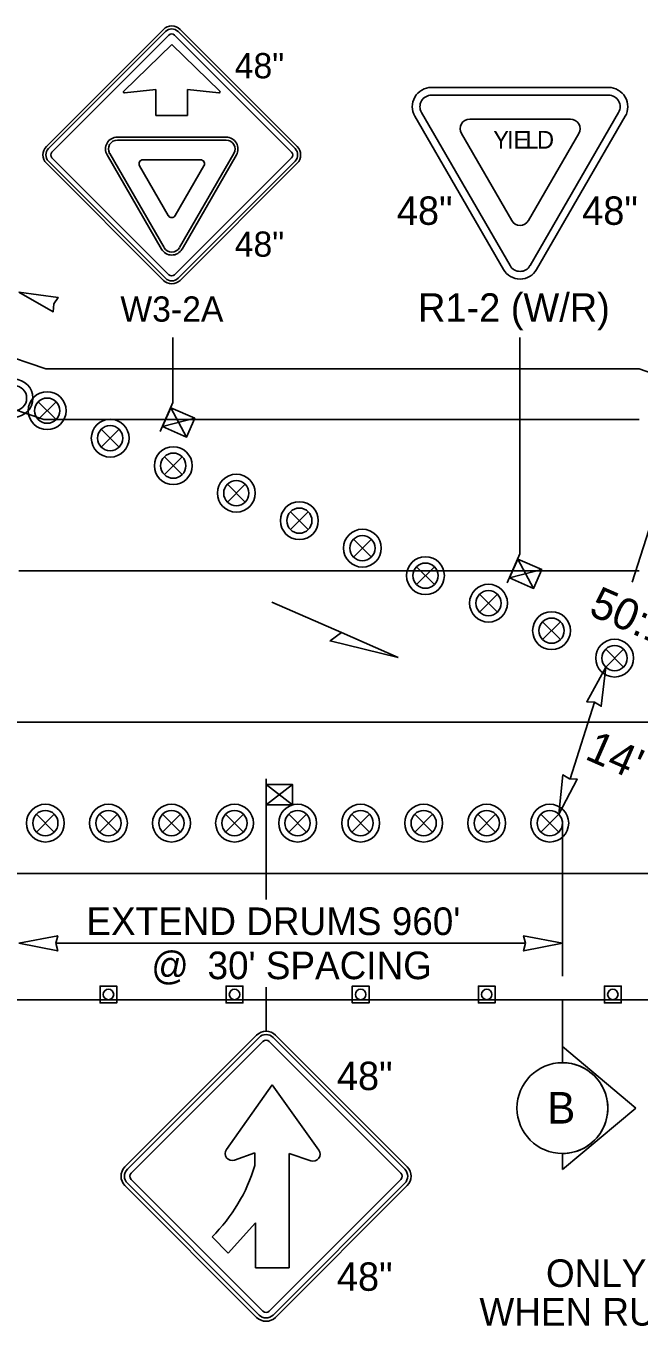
# Model space of a CAD drawing. Extents: x 99999 to 100116, y 99995 to 100013.
# Drawn here: x 100090.62 to 100092.176, y 100005.732 to 100009.03 of the extents above; entities that cross this region are included whole.
import ezdxf

# ---------------------------------------------------------------- set-up
doc = ezdxf.new("R2010")
doc.units = 0
for name, color, linetype in [('Default', 7, 'Continuous'), ('RD_MK_LineEdgeYellow', 7, 'Continuous'), ('RD_MK_LineLane', 7, 'Continuous'), ('SH_GI_SectionCut', 7, 'Continuous'), ('TR_SN_ConstructionSigns', 7, 'Continuous'), ('TR_WZ_PortableSignMount5ftMinBlk-Org', 7, 'Continuous'), ('TR_WZ_PortableSignMount5ftMinRed-Wht', 7, 'Continuous'), ('TR_WZ_TrafficCone', 7, 'Continuous'), ('TR_WZ_TrafficSafetyDrum', 7, 'Continuous'), ('TR_WZ_WorkZoneDetails', 7, 'Continuous'), ('TR_WZ_WorkZoneTextCurrent', 7, 'Continuous')]:
    doc.layers.add(name, color=color, linetype=linetype)

msp = doc.modelspace()

# ---------------------------------------------------------------- linework, layer by layer
at = {"layer": 'Default'}
for p, q in [((100090.9689, 100009.0212), (100090.6719, 100008.7242)), ((100091.3083, 100008.7242), (100091.0113, 100009.0212)), ((100090.6719, 100008.6818), (100090.9689, 100008.3848)), ((100091.0113, 100008.3848), (100091.3083, 100008.6818)), ((100091.2055, 100006.4701), (100090.8714, 100006.136)), ((100091.5873, 100006.136), (100091.2532, 100006.4701)), ((100090.8714, 100006.0883), (100091.2055, 100005.7542)), ((100091.2532, 100005.7542), (100091.5873, 100006.0883))]:
    msp.add_line(p, q, dxfattribs=at)
for centre, radius, start, end in [((100090.9901, 100009), 0.03, 45, 135), ((100090.6931, 100008.703), 0.03, 135, 225), ((100091.2871, 100008.703), 0.03, 315, 45), ((100090.9901, 100008.406), 0.03, 225, 315), ((100091.2294, 100006.4463), 0.0338, 45, 135), ((100090.8953, 100006.1122), 0.0338, 135, 225), ((100091.5635, 100006.1122), 0.0338, 315, 45), ((100091.2294, 100005.7781), 0.0338, 225, 315)]:
    msp.add_arc(centre, radius, start, end, dxfattribs=at)
at = {"layer": 'RD_MK_LineEdgeYellow'}
for p, q in [((100088.195, 100008.8663), (100090.6655, 100008.032)), ((100090.6655, 100008.032), (100092.1758, 100008.032)), ((100088.195, 100006.88), (100095.43, 100006.88))]:
    msp.add_line(p, q, dxfattribs=at)
at = {"layer": 'RD_MK_LineLane'}
for points in [[(100092.1758, 100007.648), (100090.6024, 100007.648)], [(100095.43, 100007.264), (100088.195, 100007.264)]]:
    msp.add_lwpolyline(points, dxfattribs=at)
at = {"layer": 'SH_GI_SectionCut'}
for p, q in [((100092.1583, 100007.619), (100092.3791, 100008.3098)), ((100091.9814, 100006.441), (100091.9814, 100006.56)), ((100091.9814, 100006.441), (100091.9814, 100006.4003)), ((100092.1675, 100006.2851), (100091.9814, 100006.441)), ((100091.9814, 100006.1292), (100092.1675, 100006.2851)), ((100091.9814, 100006.1699), (100091.9814, 100006.1292))]:
    msp.add_line(p, q, dxfattribs=at)
msp.add_circle((100091.9814, 100006.2851), 0.1152, dxfattribs=at)
msp.add_circle((100091.9814, 100006.2851), 0.1152, dxfattribs=at)
for start, end in [(90.0028, 269.9984), (269.9984, 90.0028), (269.9984, 90.0028)]:
    msp.add_arc((100091.9814, 100006.2851), 0.1152, start, end, dxfattribs=at)
at = {"layer": 'TR_SN_ConstructionSigns'}
for p, q in [((100090.6719, 100008.7242), (100090.9689, 100009.0212)), ((100090.9742, 100009.0159), (100090.6772, 100008.7189)), ((100091.303, 100008.7189), (100091.006, 100009.0159)), ((100091.0113, 100009.0212), (100091.3083, 100008.7242)), ((100090.686, 100008.7101), (100090.983, 100009.0071)), ((100090.9901, 100008.983), (100090.8683, 100008.8648)), ((100091.1118, 100008.8648), (100090.9901, 100008.983)), ((100090.9971, 100009.0071), (100091.2941, 100008.7101)), ((100090.8703, 100008.8605), (100090.9501, 100008.8688)), ((100090.9501, 100008.8688), (100090.9501, 100008.803)), ((100091.0301, 100008.803), (100091.0301, 100008.8688)), ((100091.0301, 100008.8688), (100091.1098, 100008.8605)), ((100092.0987, 100008.874), (100091.6491, 100008.874)), ((100091.6491, 100008.8545), (100091.6491, 100008.8547)), ((100091.6491, 100008.8547), (100091.8739, 100008.8547)), ((100091.8739, 100008.8547), (100091.6491, 100008.8547)), ((100091.6491, 100008.8547), (100091.6491, 100008.8545)), ((100090.9501, 100008.803), (100091.0301, 100008.803)), ((100091.8317, 100008.4123), (100091.6069, 100008.8009)), ((100091.6069, 100008.8009), (100091.8317, 100008.4123)), ((100091.8486, 100008.4221), (100091.6238, 100008.8107)), ((100091.6238, 100008.8107), (100091.8486, 100008.4221)), ((100091.8739, 100008.7938), (100091.7461, 100008.7938)), ((100091.7461, 100008.7938), (100091.8739, 100008.7938)), ((100092.0017, 100008.7938), (100091.8739, 100008.7938)), ((100091.8739, 100008.7938), (100092.0017, 100008.7938)), ((100092.124, 100008.8107), (100091.8992, 100008.4221)), ((100091.8992, 100008.4221), (100092.124, 100008.8107)), ((100092.1408, 100008.8009), (100091.916, 100008.4123)), ((100091.916, 100008.4123), (100092.1408, 100008.8009)), ((100091.725, 100008.7573), (100091.8528, 100008.5364)), ((100091.8528, 100008.5364), (100091.725, 100008.7573)), ((100091.895, 100008.5364), (100092.0228, 100008.7573)), ((100092.0228, 100008.7573), (100091.895, 100008.5364)), ((100091.1281, 100008.748), (100090.852, 100008.748)), ((100090.852, 100008.7405), (100091.1281, 100008.7405)), ((100091.1281, 100008.7405), (100090.852, 100008.7405)), ((100090.6772, 100008.6871), (100090.9742, 100008.3901)), ((100090.983, 100008.399), (100090.686, 100008.6959)), ((100090.8261, 100008.703), (100090.9641, 100008.4639)), ((100090.9706, 100008.4677), (100090.8326, 100008.7068)), ((100090.8326, 100008.7068), (100090.9706, 100008.4677)), ((100091.0632, 100008.6905), (100090.917, 100008.6905)), ((100090.917, 100008.6905), (100091.0632, 100008.6905)), ((100091.2941, 100008.6959), (100090.9971, 100008.399)), ((100091.006, 100008.3901), (100091.303, 100008.6871)), ((100091.1476, 100008.7068), (100091.0096, 100008.4677)), ((100091.0096, 100008.4677), (100091.1476, 100008.7068)), ((100091.0161, 100008.4639), (100091.1541, 100008.703)), ((100090.9689, 100008.3848), (100090.6719, 100008.6818)), ((100090.9083, 100008.6755), (100090.9814, 100008.5489)), ((100090.9814, 100008.5489), (100090.9083, 100008.6755)), ((100090.9987, 100008.5489), (100091.0718, 100008.6755)), ((100091.0718, 100008.6755), (100090.9987, 100008.5489)), ((100091.3083, 100008.6818), (100091.0113, 100008.3848)), ((100090.8714, 100006.136), (100091.2055, 100006.4701)), ((100091.2115, 100006.4642), (100090.8774, 100006.1301)), ((100090.8873, 100006.1201), (100091.2214, 100006.4542)), ((100091.2373, 100006.4542), (100091.5714, 100006.1201)), ((100091.5814, 100006.1301), (100091.2473, 100006.4642)), ((100091.2532, 100006.4701), (100091.5873, 100006.136)), ((100091.2453, 100006.3441), (100091.1288, 100006.1802)), ((100091.3632, 100006.1784), (100091.2453, 100006.3441)), ((100091.1493, 100006.1532), (100091.2012, 100006.1718)), ((100091.2012, 100006.1718), (100091.2012, 100006.1394)), ((100091.288, 100005.8802), (100091.288, 100006.1703)), ((100091.288, 100006.1703), (100091.3429, 100006.1513)), ((100091.2055, 100005.7542), (100090.8714, 100006.0883)), ((100090.8774, 100006.0943), (100091.2115, 100005.7602)), ((100091.2214, 100005.7701), (100090.8873, 100006.1042)), ((100091.5714, 100006.1042), (100091.2373, 100005.7701)), ((100091.2473, 100005.7602), (100091.5814, 100006.0943)), ((100091.5873, 100006.0883), (100091.2532, 100005.7542)), ((100091.1335, 100005.9171), (100091.2027, 100005.9936)), ((100091.2027, 100005.9936), (100091.2027, 100005.8802)), ((100091.0923, 100005.9583), (100091.1335, 100005.9171)), ((100091.2027, 100005.8802), (100091.288, 100005.8802))]:
    msp.add_line(p, q, dxfattribs=at)
for points in [[(100091.6491, 100008.874), (100092.0987, 100008.874)], [(100091.8739, 100008.8547), (100092.0987, 100008.8547), (100092.0987, 100008.8545)], [(100092.0987, 100008.8545), (100092.0987, 100008.8547), (100091.8739, 100008.8547)]]:
    msp.add_lwpolyline(points, dxfattribs=at)
for centre, radius, start, end in [((100090.9901, 100009), 0.03, 45, 135), ((100090.9901, 100009), 0.0225, 45, 135), ((100090.9901, 100009), 0.01, 45, 135), ((100090.8701, 100008.863), 0.0025, 134.1559, 275.9533), ((100091.1101, 100008.863), 0.0025, 264.0467, 45.8441), ((100091.6491, 100008.8253), 0.0487, 90, 210.0517), ((100091.6491, 100008.8253), 0.0487, 90, 210.0517), ((100091.6491, 100008.8253), 0.0292, 90, 210.0517), ((100091.6491, 100008.8253), 0.0292, 90, 210.0517), ((100092.0987, 100008.8253), 0.0487, 329.9522, 90), ((100092.0987, 100008.8253), 0.0487, 329.9522, 90), ((100092.0987, 100008.8253), 0.0292, 329.9522, 90), ((100092.0987, 100008.8253), 0.0292, 329.9522, 90), ((100091.7461, 100008.7695), 0.0244, 90, 210.0513), ((100091.7461, 100008.7695), 0.0244, 90, 210.0513), ((100092.0017, 100008.7695), 0.0244, 329.9514, 90), ((100092.0017, 100008.7695), 0.0244, 329.9514, 90), ((100090.6931, 100008.703), 0.03, 135, 225), ((100090.6931, 100008.703), 0.0225, 135, 225), ((100090.852, 100008.718), 0.03, 90, 210), ((100090.852, 100008.718), 0.0225, 90, 210), ((100090.852, 100008.718), 0.0225, 90, 210), ((100091.1281, 100008.718), 0.03, 330, 90), ((100091.1281, 100008.718), 0.0225, 330, 90), ((100091.1281, 100008.718), 0.0225, 330, 90), ((100091.2871, 100008.703), 0.0225, 315, 45), ((100091.2871, 100008.703), 0.03, 315, 45), ((100090.6931, 100008.703), 0.01, 135, 225), ((100090.917, 100008.6805), 0.01, 90, 210), ((100090.917, 100008.6805), 0.01, 90, 210), ((100091.0632, 100008.6805), 0.01, 330, 90), ((100091.0632, 100008.6805), 0.01, 330, 90), ((100091.2871, 100008.703), 0.01, 315, 45), ((100090.9901, 100008.5539), 0.01, 210, 330), ((100090.9901, 100008.5539), 0.01, 210, 330), ((100091.8739, 100008.5486), 0.0244, 210.0519, 329.9525), ((100091.8739, 100008.5486), 0.0244, 210.0519, 329.9525), ((100090.9901, 100008.4789), 0.03, 210, 330), ((100090.9901, 100008.4789), 0.0225, 210, 330), ((100090.9901, 100008.4789), 0.0225, 210, 330), ((100091.8739, 100008.4367), 0.0292, 210.0518, 329.9516), ((100091.8739, 100008.4367), 0.0292, 210.0518, 329.9516), ((100090.9901, 100008.406), 0.0225, 225, 315), ((100090.9901, 100008.406), 0.01, 225, 315), ((100091.8739, 100008.4367), 0.0487, 210.0518, 329.9516), ((100091.8739, 100008.4367), 0.0487, 210.0518, 329.9516), ((100090.9901, 100008.406), 0.03, 225, 315), ((100091.2294, 100006.4463), 0.0338, 45, 135), ((100091.2294, 100006.4463), 0.0253, 45, 135), ((100091.2294, 100006.4463), 0.0113, 45, 135), ((100091.1433, 100006.17), 0.0177, 144.5862, 289.6669), ((100091.3487, 100006.1681), 0.0177, 250.8938, 35.4138), ((100090.8953, 100006.1122), 0.0338, 135, 225), ((100090.8953, 100006.1122), 0.0253, 135, 225), ((100090.8953, 100006.1122), 0.0113, 135, 225), ((100090.7881, 100006.2645), 0.4316, 314.815, 343.157), ((100091.5635, 100006.1122), 0.0113, 315, 45), ((100091.5635, 100006.1122), 0.0253, 315, 45), ((100091.5635, 100006.1122), 0.0338, 315, 45), ((100091.2294, 100005.7781), 0.0338, 225, 315), ((100091.2294, 100005.7781), 0.0253, 225, 315), ((100091.2294, 100005.7781), 0.0113, 225, 315)]:
    msp.add_arc(centre, radius, start, end, dxfattribs=at)
at = {"layer": 'TR_WZ_PortableSignMount5ftMinBlk-Org'}
for p, q in [((100090.9931, 100008.0746), (100090.9611, 100008.0012)), ((100091.0279, 100007.9874), (100090.9875, 100008.0617)), ((100091.0486, 100008.0351), (100090.9667, 100008.0141)), ((100091.0077, 100008.0246), (100091.0077, 100008.0246)), ((100091.0078, 100008.0245), (100091.0078, 100008.0245)), ((100091.2294, 100007.12), (100091.2294, 100007.04)), ((100091.2961, 100007.054), (100091.2294, 100007.106)), ((100091.2961, 100007.106), (100091.2294, 100007.054)), ((100091.2627, 100007.08), (100091.2627, 100007.08)), ((100091.2628, 100007.08), (100091.2628, 100007.08))]:
    msp.add_line(p, q, dxfattribs=at)
for points in [[(100091.0279, 100007.9874), (100091.0486, 100008.0351), (100090.9875, 100008.0617), (100090.9667, 100008.0141)], [(100090.9875, 100008.0617), (100091.0486, 100008.0351), (100091.0279, 100007.9874), (100090.9667, 100008.0141)], [(100091.2961, 100007.054), (100091.2961, 100007.106), (100091.2294, 100007.106), (100091.2294, 100007.054)], [(100091.2294, 100007.106), (100091.2961, 100007.106), (100091.2961, 100007.054), (100091.2294, 100007.054)]]:
    msp.add_lwpolyline(points, close=True, dxfattribs=at)
at = {"layer": 'TR_WZ_PortableSignMount5ftMinRed-Wht'}
for p, q in [((100091.8736, 100007.6907), (100091.8416, 100007.6174)), ((100091.9083, 100007.6035), (100091.868, 100007.6778)), ((100091.9291, 100007.6511), (100091.8472, 100007.6302)), ((100091.8881, 100007.6407), (100091.8881, 100007.6407)), ((100091.8882, 100007.6406), (100091.8882, 100007.6406))]:
    msp.add_line(p, q, dxfattribs=at)
for points in [[(100091.9083, 100007.6035), (100091.9291, 100007.6511), (100091.868, 100007.6778), (100091.8472, 100007.6302)], [(100091.868, 100007.6778), (100091.9291, 100007.6511), (100091.9083, 100007.6035), (100091.8472, 100007.6302)]]:
    msp.add_lwpolyline(points, close=True, dxfattribs=at)
at = {"layer": 'TR_WZ_TrafficCone'}
for points in [[(100090.8081, 100006.552), (100090.8507, 100006.552), (100090.8507, 100006.5947), (100090.8081, 100006.5947), (100090.8081, 100006.552)], [(100090.8081, 100006.5947), (100090.8507, 100006.5947), (100090.8507, 100006.552), (100090.8081, 100006.552), (100090.8081, 100006.5947)], [(100091.1281, 100006.552), (100091.1707, 100006.552), (100091.1707, 100006.5947), (100091.1281, 100006.5947), (100091.1281, 100006.552)], [(100091.1281, 100006.5947), (100091.1707, 100006.5947), (100091.1707, 100006.552), (100091.1281, 100006.552), (100091.1281, 100006.5947)], [(100091.4481, 100006.552), (100091.4907, 100006.552), (100091.4907, 100006.5947), (100091.4481, 100006.5947), (100091.4481, 100006.552)], [(100091.4481, 100006.5947), (100091.4907, 100006.5947), (100091.4907, 100006.552), (100091.4481, 100006.552), (100091.4481, 100006.5947)], [(100091.7681, 100006.552), (100091.8107, 100006.552), (100091.8107, 100006.5947), (100091.7681, 100006.5947), (100091.7681, 100006.552)], [(100091.7681, 100006.5947), (100091.8107, 100006.5947), (100091.8107, 100006.552), (100091.7681, 100006.552), (100091.7681, 100006.5947)], [(100092.0881, 100006.552), (100092.1307, 100006.552), (100092.1307, 100006.5947), (100092.0881, 100006.5947), (100092.0881, 100006.552)], [(100092.0881, 100006.5947), (100092.1307, 100006.5947), (100092.1307, 100006.552), (100092.0881, 100006.552), (100092.0881, 100006.5947)]]:
    msp.add_lwpolyline(points, dxfattribs=at)
for centre in [(100090.8294, 100006.5734), (100091.1494, 100006.5734), (100091.4694, 100006.5734), (100091.7894, 100006.5734), (100092.1094, 100006.5734)]:
    msp.add_circle(centre, 0.0133, dxfattribs=at)
at = {"layer": 'TR_WZ_TrafficSafetyDrum'}
for p, q in [((100090.6513, 100008.0316), (100090.6966, 100008.0768)), ((100090.6966, 100008.0316), (100090.6513, 100008.0768)), ((100090.8113, 100007.9618), (100090.8566, 100008.0071)), ((100090.8566, 100007.9618), (100090.8113, 100008.0071)), ((100090.9713, 100007.8921), (100091.0166, 100007.9373)), ((100091.0166, 100007.8921), (100090.9713, 100007.9373)), ((100091.1313, 100007.8223), (100091.1766, 100007.8676)), ((100091.1766, 100007.8223), (100091.1313, 100007.8676)), ((100091.2913, 100007.7526), (100091.3366, 100007.7978)), ((100091.3366, 100007.7526), (100091.2913, 100007.7978)), ((100091.4513, 100007.6828), (100091.4966, 100007.7281)), ((100091.4966, 100007.6828), (100091.4513, 100007.7281)), ((100091.6113, 100007.6131), (100091.6566, 100007.6584)), ((100091.6566, 100007.6131), (100091.6113, 100007.6584)), ((100091.7713, 100007.5434), (100091.8166, 100007.5886)), ((100091.8166, 100007.5434), (100091.7713, 100007.5886)), ((100091.9313, 100007.4736), (100091.9766, 100007.5189)), ((100091.9766, 100007.4736), (100091.9313, 100007.5189)), ((100092.0913, 100007.4039), (100092.1366, 100007.4491)), ((100092.1366, 100007.4039), (100092.0913, 100007.4491)), ((100090.6468, 100006.9854), (100090.692, 100007.0306)), ((100090.692, 100006.9854), (100090.6468, 100007.0306)), ((100090.8068, 100006.9854), (100090.852, 100007.0306)), ((100090.852, 100006.9854), (100090.8068, 100007.0306)), ((100090.9668, 100006.9854), (100091.012, 100007.0306)), ((100091.012, 100006.9854), (100090.9668, 100007.0306)), ((100091.1268, 100006.9854), (100091.172, 100007.0306)), ((100091.172, 100006.9854), (100091.1268, 100007.0306)), ((100091.2868, 100006.9854), (100091.332, 100007.0306)), ((100091.332, 100006.9854), (100091.2868, 100007.0306)), ((100091.4468, 100006.9854), (100091.492, 100007.0306)), ((100091.492, 100006.9854), (100091.4468, 100007.0306)), ((100091.6068, 100006.9854), (100091.652, 100007.0306)), ((100091.652, 100006.9854), (100091.6068, 100007.0306)), ((100091.7668, 100006.9854), (100091.812, 100007.0306)), ((100091.812, 100006.9854), (100091.7668, 100007.0306)), ((100091.9268, 100006.9854), (100091.972, 100007.0306)), ((100091.972, 100006.9854), (100091.9268, 100007.0306))]:
    msp.add_line(p, q, dxfattribs=at)
for centre, radius in [((100090.5899, 100008.086), 0.048), ((100090.5899, 100008.086), 0.048), ((100090.5899, 100008.086), 0.032), ((100090.6739, 100008.0542), 0.048), ((100090.6739, 100008.0542), 0.048), ((100090.6739, 100008.0542), 0.032), ((100090.8339, 100007.9845), 0.048), ((100090.8339, 100007.9845), 0.048), ((100090.8339, 100007.9845), 0.032), ((100090.9939, 100007.9147), 0.048), ((100090.9939, 100007.9147), 0.048), ((100090.9939, 100007.9147), 0.032), ((100091.1539, 100007.845), 0.048), ((100091.1539, 100007.845), 0.048), ((100091.1539, 100007.845), 0.032), ((100091.3139, 100007.7752), 0.048), ((100091.3139, 100007.7752), 0.048), ((100091.3139, 100007.7752), 0.032), ((100091.4739, 100007.7055), 0.048), ((100091.4739, 100007.7055), 0.048), ((100091.4739, 100007.7055), 0.032), ((100091.6339, 100007.6357), 0.048), ((100091.6339, 100007.6357), 0.048), ((100091.6339, 100007.6357), 0.032), ((100091.7939, 100007.566), 0.048), ((100091.7939, 100007.566), 0.048), ((100091.7939, 100007.566), 0.032), ((100091.9539, 100007.4962), 0.048), ((100091.9539, 100007.4962), 0.048), ((100091.9539, 100007.4962), 0.032), ((100092.1139, 100007.4265), 0.048), ((100092.1139, 100007.4265), 0.048), ((100092.1139, 100007.4265), 0.032), ((100090.6694, 100007.008), 0.048), ((100090.6694, 100007.008), 0.048), ((100090.6694, 100007.008), 0.032), ((100090.8294, 100007.008), 0.048), ((100090.8294, 100007.008), 0.048), ((100090.8294, 100007.008), 0.032), ((100090.9894, 100007.008), 0.048), ((100090.9894, 100007.008), 0.048), ((100090.9894, 100007.008), 0.032), ((100091.1494, 100007.008), 0.048), ((100091.1494, 100007.008), 0.048), ((100091.1494, 100007.008), 0.032), ((100091.3094, 100007.008), 0.048), ((100091.3094, 100007.008), 0.048), ((100091.3094, 100007.008), 0.032), ((100091.4694, 100007.008), 0.048), ((100091.4694, 100007.008), 0.048), ((100091.4694, 100007.008), 0.032), ((100091.6294, 100007.008), 0.048), ((100091.6294, 100007.008), 0.048), ((100091.6294, 100007.008), 0.032), ((100091.7894, 100007.008), 0.048), ((100091.7894, 100007.008), 0.048), ((100091.7894, 100007.008), 0.032), ((100091.9494, 100007.008), 0.048), ((100091.9494, 100007.008), 0.048), ((100091.9494, 100007.008), 0.032)]:
    msp.add_circle(centre, radius, dxfattribs=at)
at = {"layer": 'TR_WZ_WorkZoneDetails'}
for p, q in [((100088.195, 100009.0015), (100090.6703, 100008.16)), ((100090.9931, 100008.0746), (100090.9931, 100008.24)), ((100091.8736, 100007.6907), (100091.8738, 100008.24)), ((100090.6703, 100008.16), (100092.1758, 100008.16)), ((100092.1758, 100008.16), (100092.7368, 100007.968)), ((100091.4207, 100007.4911), (100091.2441, 100007.5687)), ((100092.0007, 100007.1203), (100092.0628, 100007.3146)), ((100091.2294, 100007.04), (100091.2294, 100006.8141)), ((100091.9814, 100006.6197), (100091.9814, 100007.0134)), ((100091.8876, 100006.7031), (100090.6962, 100006.7031)), ((100091.2294, 100006.5921), (100091.2294, 100006.48)), ((100088.195, 100006.56), (100095.43, 100006.56))]:
    msp.add_line(p, q, dxfattribs=at)
for points in [[(100090.6024, 100008.355), (100090.6893, 100008.3051), (100090.6912, 100008.3249), (100090.7017, 100008.3416)], [(100091.5646, 100007.4278), (100091.3919, 100007.47), (100091.4207, 100007.4911)], [(100092.0913, 100007.4039), (100092.0433, 100007.316), (100092.063, 100007.3145), (100092.08, 100007.3044)], [(100091.972, 100007.0306), (100091.9821, 100007.1303), (100091.9992, 100007.1203), (100092.019, 100007.1191)], [(100090.6024, 100006.7031), (100090.7007, 100006.6838), (100090.6962, 100006.7031), (100090.7007, 100006.7224)], [(100091.9814, 100006.7031), (100091.8831, 100006.6838), (100091.8876, 100006.7031), (100091.8831, 100006.7224)]]:
    msp.add_lwpolyline(points, close=True, dxfattribs=at)

# ---------------------------------------------------------------- texts
at = {"layer": 'Default'}
for s, p in [('Y', (100091.8057, 100008.7189)), ('I', (100091.8408, 100008.7189)), ('E', (100091.857, 100008.7189)), ('L', (100091.8876, 100008.7189)), ('D', (100091.9168, 100008.7189))]:
    msp.add_text(s, height=0.045, dxfattribs=at).set_placement(p)
at = {"layer": 'SH_GI_SectionCut'}
msp.add_text('B', height=0.08, rotation=359.9906, dxfattribs=at).set_placement((100091.9427, 100006.2458))
at = {"layer": 'TR_SN_ConstructionSigns'}
for s, height, p in [('48"', 0.064, (100091.1499, 100008.8973)), ('48"', 0.072, (100091.5613, 100008.5256)), ('48"', 0.072, (100092.0316, 100008.5256)), ('48"', 0.064, (100091.1499, 100008.4447)), ('R1-2 (W/R)', 0.072, (100091.6151, 100008.28)), ('W3-2A', 0.064, (100090.8597, 100008.28))]:
    msp.add_text(s, height=height, dxfattribs=at).set_placement(p)
for p in [(100091.4092, 100006.3307), (100091.4092, 100005.8216)]:
    msp.add_text('48"', height=0.072, rotation=360, dxfattribs=at).set_placement(p)
at = {"layer": 'TR_WZ_WorkZoneDetails'}
for s, p in [('ONLY USED', (100091.9397, 100005.8313)), ('WHEN RUMBLE', (100091.7709, 100005.7333))]:
    msp.add_text(s, height=0.07, dxfattribs=at).set_placement(p)
at = {"layer": 'TR_WZ_WorkZoneTextCurrent'}
for s, rotation, p in [('50:1 TAPER', 336.4269, (100092.0451, 100007.5375)), ("14' MIN", 336.2762, (100092.0356, 100007.1718))]:
    msp.add_text(s, height=0.08, rotation=rotation, dxfattribs=at).set_placement(p)
for s, p in [("EXTEND DRUMS 960'", (100090.7735, 100006.7241)), ('@', (100090.9382, 100006.6121)), ("30' SPACING", (100091.0809, 100006.6121))]:
    msp.add_text(s, height=0.07, dxfattribs=at).set_placement(p)

doc.saveas('drawing.dxf')
